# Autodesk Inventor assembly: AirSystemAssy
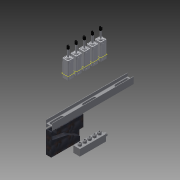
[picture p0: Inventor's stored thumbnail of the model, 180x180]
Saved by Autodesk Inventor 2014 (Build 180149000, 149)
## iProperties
Shininess: 64.0
Length Units: 11272
Angle Units: 11279
Time Units: 11290
Mass Units: 11286
Length Display Precision: 3
Angle Display Precision: 2
Compacted: True
Part Number: AirSystemAssy
Document SubType Name: Assembly
Created: 2003-01
Designer: dayb
Mass: 3019.53 g
Surface Area: 6641.07 cm^2
Volume: 3019.53 cm^3
Density: 1 g/cm^3
Density: 0.0
Volumn: 0.0
Area: 0.0
PropertySet Name: Model Information
Control State: 0
Master: False
Checked Out: False
Author: dayb
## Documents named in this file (5)
- C:\Users\iTools\Desktop\tutorial files\Tube and Pipe\Air System\AirSystemAssy.iam
- C:\Users\iTools\Desktop\tutorial files\Tube and Pipe\Air System\AirValve.ipt
- C:\Users\iTools\Desktop\tutorial files\Tube and Pipe\Air System\IBeam.ipt
- C:\Users\iTools\Desktop\tutorial files\Tube and Pipe\Air System\path.ipt
- C:\Users\iTools\Desktop\tutorial files\Tube and Pipe\Air System\AirCylinder.iam
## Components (8 placed, 4 different names)
1. AirValve:1 — Mate:1, Flush:1, Mate:2, Flush:2
2. IBeam:1 — Mate:1, Flush:1
3. path:1 — Flush:3, Flush:4, Flush:5
4. AirCylinder:1 [sub-assembly] — Mate:2, Flush:2
5. AirCylinder:2 [sub-assembly]
6. AirCylinder:3 [sub-assembly]
7. AirCylinder:4 [sub-assembly]
8. AirCylinder:5 [sub-assembly]
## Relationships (7: Flush 5, Mate 2)
- Mate:1: AirValve:1 ↔ IBeam:1
- Flush:1: AirValve:1 ↔ IBeam:1
- Mate:2: AirValve:1 ↔ AirCylinder:1
- Flush:2: AirValve:1 ↔ AirCylinder:1
- Flush:3: path:1
- Flush:4: path:1
- Flush:5: path:1
